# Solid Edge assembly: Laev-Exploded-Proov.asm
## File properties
Author: Egon 815
Template: Normal.asm
Last saved by: Egon 815
Revision: 74
Application: Solid Edge
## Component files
Jubin.psm
SuurKahur.par
ljeKahur_mir2.par
JuhtimisKeskus.par
Korsten.par
Radar.par
Raketid.par
Raketikorpus.par
LaevaKere12.par
SuurKruvi.par
Mootor.par
Dekk1.par
Dekk2.par
ljeKahur.par
ris.par
AlusJoonised.par
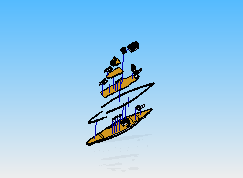
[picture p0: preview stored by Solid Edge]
